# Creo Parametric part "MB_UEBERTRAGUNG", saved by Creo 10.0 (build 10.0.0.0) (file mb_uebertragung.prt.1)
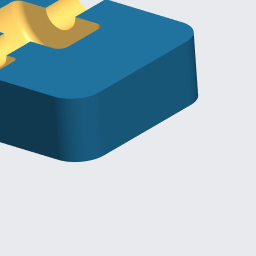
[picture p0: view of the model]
Materials in the file: S235JRG2

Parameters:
  BENENNUNG = "XXX"
  DATUM = "XX.XX.XX"
  ERSTELLER = "ARINDA"
  TEILETYP = "Fertigungsteil"
  PTC_MASTER_MATERIAL = "S235JRG2"
  SELECT_EN_NAME = "S235JRG2"
  SELECT_DIN_NAME = "RSt37-2"
  SELECT_DIN_NUMBER = "1.0038"
  SELECT_ASTM_NAME = "A 283 M Grade 2"
  MATERIAL_GROUP = "ME_ST_Baustahl"
  STANDARD_EN_DELIVERYSPEC = "DIN EN 10025"
  STANDARD_DIN_DELIVERYSPEC = "DIN 17100"

Other parameters: MASSE

Created from: KURVENAUSWAHL.PRT

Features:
  1. coordinate system
  2. datum plane "T_RECHTS_Y-Z"
  3. datum plane "T_OBEN_X-Z"
  4. datum plane "T_VORNE_X-Y"
  5. datum axis
  6. datum axis
  7. datum axis
  8. protrusion
  9. round
  10. revolve "Drehen 1"
  11. feature "Körper Subtrahieren 1"

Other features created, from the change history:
  sketch "Skizze 2"
  curve "Kurve 2"
  extrusion "Profil 2"
  datum plane "DTM1" (2 times)
  sketch "Skizze 3"

Other named items: T_BASIC, T_X-ACHSE, T_Y-ACHSE, T_Z-ACHSE

Layers: 00_STD-ACHSEN, 00_STD-EBENEN, 00_STD-KOORDSYS, 01_ACHSEN, 01_EBENEN, 01_KURVEN, KURVENELEMENTE, VOLUMENGEOMETRIE

Surfaces: 9 plane, 8 cylinder, 3 torus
